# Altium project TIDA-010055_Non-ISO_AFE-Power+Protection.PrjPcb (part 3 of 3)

## Sheet TIDA-010055_Non-ISO_AFE-Power+Protection _Pg7.SchDoc: +24V INPUT SIMPLE SWITCHER + POWER MUX + MONITOR
size 431 x 279 mm; Date: Not shown in title block; ApprovedBy: Not shown in title block; CheckedBy: Not shown in title block; Author: Not shown in title block; CompanyName: Not shown in title block; DrawnBy: Sreenivasa; Engineer: Not shown in title block; Organization: Not shown in title block; Address1: Not shown in title block; Address2: Not shown in title block; Address3: Not shown in title block; Address4: Not shown in title block; DocumentNumber: 1; Revision: Use project parameter SCH_Rev; SheetNumber: 7; SheetTotal: 9; PageSetup: Record=PageOptions¦CenterHorizontal=True¦CenterVertical=True¦PrintScale=0.62¦XCorrection=1.00¦YCorrection=1.00¦PrintKind=0¦BorderSize=5000000¦LeftOffset=0¦BottomOffset=0¦Orientation=2¦PaperLength=1000¦PaperWidth=1000¦Scale=100¦PaperSource=15¦PrintQuality=600¦MediaType=1¦DitherType=10¦PrintScaleMode=1¦PaperKind=Letter
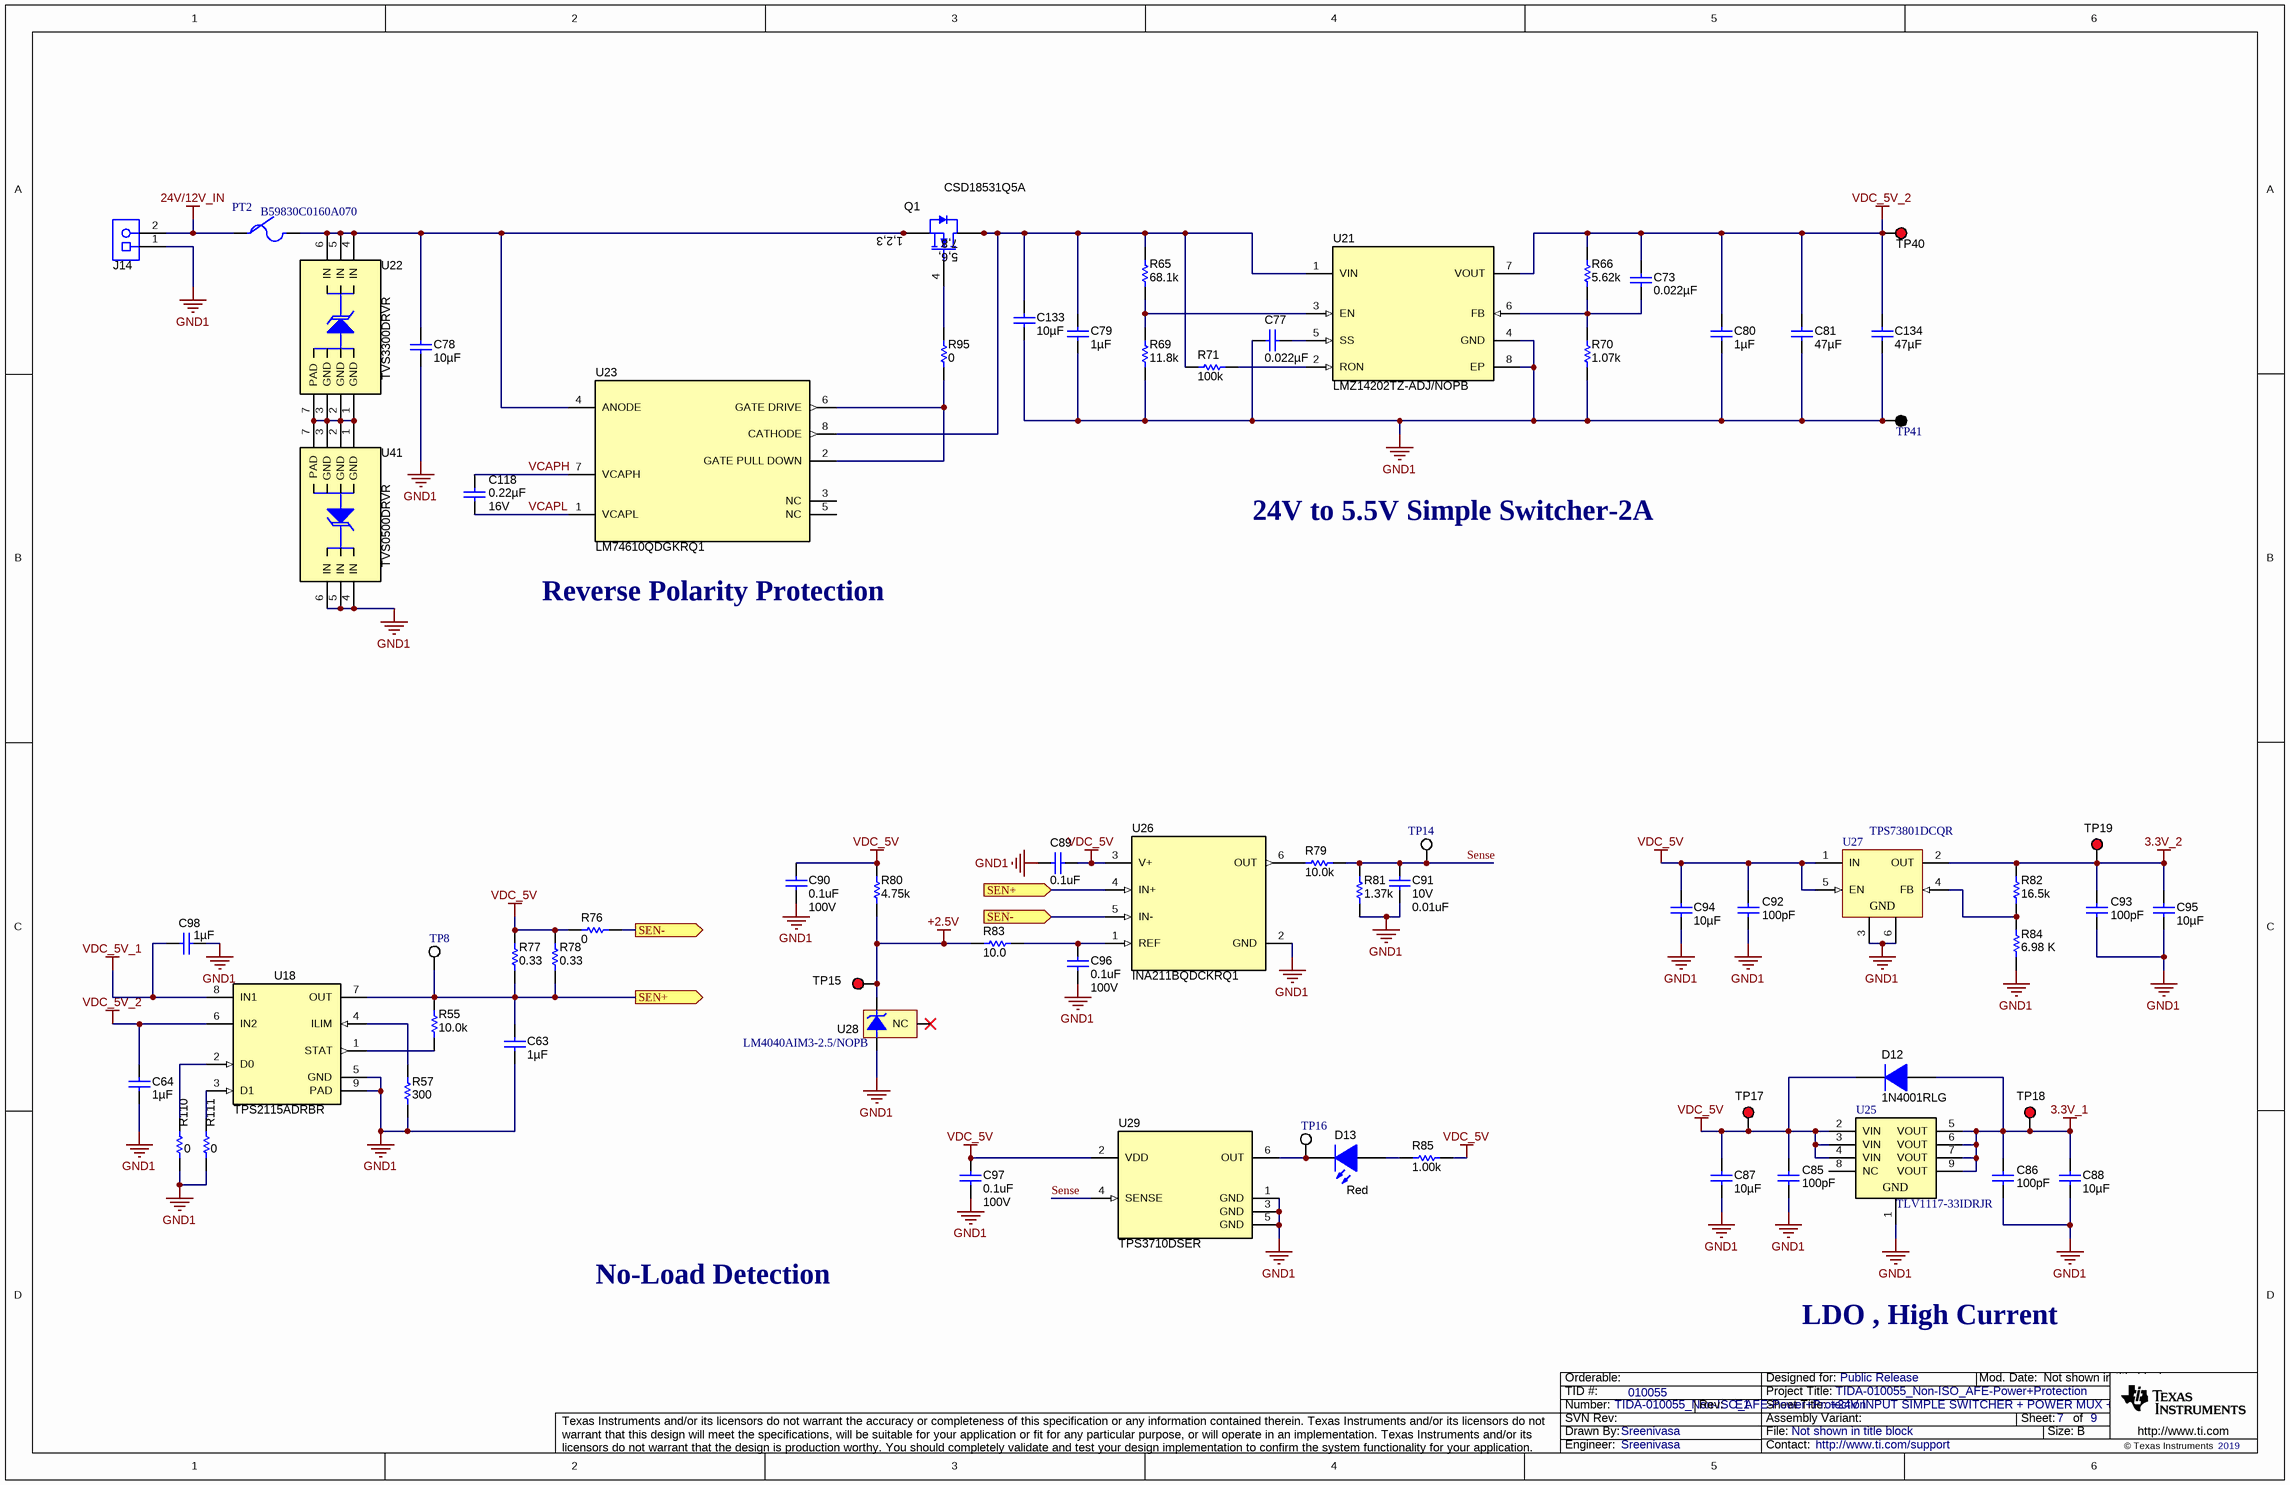
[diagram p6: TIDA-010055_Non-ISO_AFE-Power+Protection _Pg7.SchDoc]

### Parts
C63  ValueDisplayed: 1µF  [0603S]  (hidden comment: CGA3E1X7R1E105K080AC)
C64  ValueDisplayed: 1µF  [0603S]  (hidden comment: CGA3E1X7R1E105K080AC)
C73  ValueDisplayed: 0.022µF  [0805_HV]  (hidden comment: 08051C223JAT2A)
C77  ValueDisplayed: 0.022µF  [0805_HV]  (hidden comment: 08051C223JAT2A)
C78  ValueDisplayed: 10µF  [1210_270]  (hidden comment: C3225X7S1H106M250AB)
C79  ValueDisplayed: 1µF  [0603]  (hidden comment: UMK107BJ105KA-T)
C80  ValueDisplayed: 1µF  [0603]  (hidden comment: UMK107BJ105KA-T)
C81  ValueDisplayed: 47µF  [1206]  (hidden comment: EMK316BBJ476ML-T)
C85  ValueDisplayed: 100pF  [0603]  (hidden comment: 06031A101GAT2A)
C86  ValueDisplayed: 100pF  [0603]  (hidden comment: 06031A101GAT2A)
C87  ValueDisplayed: 10µF  [0805_HV]  (hidden comment: C2012X5R1E106K085AC)
C88  ValueDisplayed: 10µF  [0805_HV]  (hidden comment: C2012X5R1E106K085AC)
C89  ValueDisplayed: 0.1uF  [0805_HV]  (hidden comment: CMP-0007886-2)
C90  ValueDisplayed: 0.1uF  VDC_V: 100V  [0805_HV]  (hidden comment: CMP-0007886-2)
C91  VDC_V: 10V  ValueDisplayed: 0.01uF  [0603]  (hidden comment: 0603ZC103KAT2A)
C92  ValueDisplayed: 100pF  [0603]  (hidden comment: 06031A101GAT2A)
C93  ValueDisplayed: 100pF  [0603]  (hidden comment: 06031A101GAT2A)
C94  ValueDisplayed: 10µF  [0805_HV]  (hidden comment: C2012X5R1E106K085AC)
C95  ValueDisplayed: 10µF  [0805_HV]  (hidden comment: C2012X5R1E106K085AC)
C96  ValueDisplayed: 0.1uF  VDC_V: 100V  [0805_HV]  (hidden comment: CMP-0007886-2)
C97  ValueDisplayed: 0.1uF  VDC_V: 100V  [0805_HV]  (hidden comment: CMP-0007886-2)
C98  ValueDisplayed: 1µF  [0603S]  (hidden comment: CGA3E1X7R1E105K080AC)
C118  ValueDisplayed: 0.22µF  Value2: 16V  [0805_HV]  (hidden comment: 0805YC224KAT2A)
C133  ValueDisplayed: 10µF  [1210_270]  (hidden comment: C3225X7S1H106M250AB)
C134  ValueDisplayed: 47µF  [1206]  (hidden comment: EMK316BBJ476ML-T)
D12  1N4001RLG  [DO-41]
D13  value Red  [LED_LTST-C170_Red]  (hidden comment: CMP-0002829-2)
J14  1751248  [CONN_1751248]  (value not drawn)
PT2  B59830C0160A070  [POLYSWITCH_RXE135]
Q1  CSD18531Q5A  [DQJ0008A]
R55  ValueDisplayed: 10.0k  [0603]  (hidden comment: CRCW060310K0FKEA)
R57  ValueDisplayed: 300  [0603]  (hidden comment: RC0603FR-07300RL)
R65  ValueDisplayed: 68.1k  [0805_HV]  (hidden comment: ERJ-6ENF6812V)
R66  ValueDisplayed: 5.62k  [0805_HV]  (hidden comment: RT0805BRD075K62L)
R69  ValueDisplayed: 11.8k  [0805_HV]  (hidden comment: ERJ-6ENF1182V)
R70  ValueDisplayed: 1.07k  [0805_HV]  (hidden comment: ERJ-6ENF1071V)
R71  ValueDisplayed: 100k  [0805_HV]  (hidden comment: MCU08050C1003FP500)
R76  ValueDisplayed: 0  [0603]  (hidden comment: ERJ-3GEY0R00V)
R77  ValueDisplayed: 0.33  [1206]  (hidden comment: CSR1206FKR330)
R78  ValueDisplayed: 0.33  [1206]  (hidden comment: CSR1206FKR330)
R79  ValueDisplayed: 10.0k  [0603]  (hidden comment: CMP-0021998-2)
R80  ValueDisplayed: 4.75k  [0603]  (hidden comment: CMP-0022456-2)
R81  ValueDisplayed: 1.37k  [0603]  (hidden comment: RC0603FR-071K37L)
R82  ValueDisplayed: 16.5k  [0603]  (hidden comment: RC0603FR-0716K5L)
R83  ValueDisplayed: 10.0  [0603]  (hidden comment: CRCW060310R0FKEAHP)
R84  ValueDisplayed: 6.98 K  [0603]  (hidden comment: RT0603DRD076K98L)
R85  ValueDisplayed: 1.00k  [0603]  (hidden comment: ERJ-3EKF1001V)
R95  ValueDisplayed: 0  [0805_HV]  (hidden comment: CRCW08050000Z0EA)
R110  ValueDisplayed: 0  [0603]  (hidden comment: ERJ-3GEY0R00V)
R111  ValueDisplayed: 0  [0603]  (hidden comment: ERJ-3GEY0R00V)
TP8  5002  [Keystone5002]  (value not drawn)
TP14  5002  [Keystone5002]  (value not drawn)
TP15  5000  [Keystone5000]  (value not drawn)
TP16  5002  [Keystone5002]  (value not drawn)
TP17  5000  [Keystone5000]  (value not drawn)
TP18  5000  [Keystone5000]  (value not drawn)
TP19  5000  [Keystone5000]  (value not drawn)
TP40  5000  [Keystone5000]  (value not drawn)
TP41  5001  [Keystone5001]  (value not drawn)
U18  TPS2115ADRBR  [DRB0008B]
U21  LMZ14202TZ-ADJ/NOPB  [NDW0007A]
U22  TVS3300DRVR  [DRV0006A]
U23  LM74610QDGKRQ1  [DGK0008A_N]
U25  TLV1117-33IDRJR  [DRJ0008A]
U26  INA211BQDCKRQ1  [DCK0006A_L]
U27  TPS73801DCQR  [DCQ0006A_N]
U28  LM4040AIM3-2.5/NOPB  [MF03A_N]
U29  TPS3710DSER  [DSE0006A]
U41  TVS0500DRVR  [DRV0006A]

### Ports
SEN+ (in), SEN+ (out), SEN- (in), SEN- (out)

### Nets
3.3V_1: C86.2 C88.2 D12.2(A) TP18.1 U25.5(VOUT) U25.6(VOUT) U25.7(VOUT) U25.9(VOUT)
3.3V_2: C93.2 C95.2 R82.2 TP19.1 U27.2(OUT)
24V/12V_IN: J14.2 PT2.1
+2.5V: R80.1 R83.1 TP15.1 U28.1(+V)
GND1: C63.2 C64.2 C77.2 C78.2 C79.2 C80.2 C81.2 C85.1 C86.1 C87.1 C88.1 C89.1 C90.1 C91.2 C92.1 C93.1 C94.1 C95.1 C96.1 C97.1 C98.2 C133.2 C134.2 J14.1 R57.1 R69.1 R70.1 R81.1 R84.1 R110.1 R111.1 TP41.1 U18.5(GND) U18.9(PAD) U21.4(GND) U21.8(EP) U25.1(GND) U26.2(GND) U27.3(GND) U27.6(GND) U28.2(-V) U29.1(GND) U29.3(GND) U29.5(GND) U41.4(IN) U41.5(IN) U41.6(IN)
VDC_5V: C85.2 C87.2 C89.2 C90.2 C92.2 C94.2 C97.2 D12.1(K) R76.1 R77.2 R78.2 R80.2 R85.2 TP17.1 U25.2(VIN) U25.3(VIN) U25.4(VIN) U26.3(V+) U27.1(IN) U27.5(EN) U29.2(VDD)
VDC_5V_1: C98.1 U18.8(IN1)
VDC_5V_2: C64.1 C73.1 C80.1 C81.1 C134.1 R66.2 TP40.1 U18.6(IN2) U21.7(VOUT)
SEN+: C63.1 R55.2 R77.1 R78.1 TP8.1 U18.7(OUT) U26.4(IN+) ; port SEN+
SEN-: R76.2 U26.5(IN-) ; port SEN-
Sense: C91.1 R79.2 R81.2 TP14.1 U29.4(SENSE)
VCAPH: C118.1 U23.7(VCAPH)
VCAPL: C118.2 U23.1(VCAPL)
NetC73_2: C73.2 R66.1 R70.2 U21.6(FB)
NetC77_1: C77.1 U21.5(SS)
NetC78_1: C78.1 PT2.2 Q1.1(S) Q1.2(S) Q1.3(S) U22.4(IN) U22.5(IN) U22.6(IN) U23.4(ANODE)
NetC79_1: C79.1 C133.1 Q1.5(D) Q1.6(D) Q1.7(D) Q1.8(D) Q1.9(D) R65.2 R71.2 U21.1(VIN) U23.8(CATHODE)
NetC96_2: C96.2 R83.2 U26.1(REF)
NetD13_1: D13.1(A) R85.1
NetD13_2: D13.2(K) TP16.1 U29.6(OUT)
NetQ1_4: Q1.4(G) R95.2
NetR55_1: R55.1 U18.1(STAT)
NetR57_2: R57.2 U18.4(ILIM)
NetR65_1: R65.1 R69.2 U21.3(EN)
NetR71_1: R71.1 U21.2(RON)
NetR79_1: R79.1 U26.6(OUT)
NetR82_1: R82.1 R84.2 U27.4(FB)
NetR95_1: R95.1 U23.2(GATE_PULL_DOWN) U23.6(GATE_DRIVE)
NetR110_2: R110.2 U18.2(D0)
NetR111_2: R111.2 U18.3(D1)
NetU22_1: U22.1(GND) U22.2(GND) U22.3(GND) U22.7(PAD) U41.1(GND) U41.2(GND) U41.3(GND) U41.7(PAD)

Not connected (* = marked no-connect by the designer): U23 3(NC) 5(NC); U25 8(NC); U28 3(NC)*

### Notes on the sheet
- 24V to 5.5V Simple Switcher-2A
- Reverse Polarity Protection
- No-Load Detection
- LDO , High Current

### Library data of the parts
C63 C64 C98 = GRM188R71E105KA12D: CAP, CERM, 1 µF, 25 V, +/- 10%, X7R, 0603; Manufacturer: TDK Corporation; Polarized: N; CompType: Capacitor; Value: 1uF; U/M: EA; Cap_F: 0.000001; Tolerance_%: 10; Value1: Unknown; VDC_V: 25; Value2: 25V; TaMin_C: -55; TaMax_C: 125; Cap_Case: 0603; AEC Category: Q200
C73 C77 = 08051C223JAT2A: CAP, CERM, 0.022 µF, 100 V,+/- 5%, X7R, 0805; Manufacturer: AVX; Polarized: N; CompType: Capacitor; Value: 0.022uF; U/M: EA; Cap_F: 0.000000022; Tolerance_%: 5; ESR_ohm: 0.052; Value1: 0.052 ohm; VDC_V: 100; Value2: 100V; TaMin_C: -55; TaMax_C: 125; Cap_Case: 0805; SizeArea_mm2: 2.5; SizeAreaWB_mm2: 6.75; SizeX_mm: 2; SizeY_mm: 1.25; SizeZ_mm: 1.45; AEC Category: Q200; Green_Lifecycle: Active; Green_REACh: Passed
C78 C133 = GRM32ER71J106KA12L: CAP, CERM, 10µF ±20% 50V Ceramic Capacitor X7R 1210; Manufacturer: Taiyo Yuden; Polarized: N; Value: 10uF; U/M: EA; Cap_F: 0.00001; Tolerance_%: 10; Value1: Unknown; VDC_V: 63; Value2: 63V; TaMin_C: -55; TaMax_C: 125; Cap_Case: 1210; SizeArea_mm2: 8; SizeAreaWB_mm2: 14.7; SizeX_mm: 3.2; SizeY_mm: 2.5; SizeZ_mm: 2.7; AEC Category: Q200
C79 C80 = UMK107AB7105KA-T: CAP, CERM,  1UF 50V X5R 0603; Manufacturer: Taiyo Yuden; Polarized: N; CompType: Capacitor; U/M: EA; Cap_F: 0.000001; Tolerance_%: 10; VDC_V: 50; TempCo: X7R; TaMin_C: -55; TaMax_C: 125; SizeArea_mm2: 1.28; SizeAreaWB_mm2: 4.68; SizeX_mm: 1.6; SizeY_mm: 0.8; SizeZ_mm: 1; AEC Category: Q200; Green_Lifecycle: Active; Green_REACh: Passed
C81 = C3216X5R1C476M160AB: CAP, CERM,47µF ±20% 16V Ceramic Capacitor JB 1206; Manufacturer: Taiyo Yuden; Polarized: N; Value: 47uF; U/M: EA; Cap_F: 0.000047; Tolerance_%: 15; VDC_V: 16; TempCo: X5R; TaMin_C: -55; TaMax_C: 85; SizeArea_mm2: 5.12; SizeAreaWB_mm2: 10.92; SizeX_mm: 3.2; SizeY_mm: 1.6; SizeZ_mm: 1.35; AEC Category: Q200; Green_Lifecycle: Active; Green_REACh: Passed
C85 C86 C92 C93 = 06035A101JAT2A: CAP, CERM, 100 pF, 50 V, +/- 5%, C0G/NP0, 0603; Manufacturer: AVX; Polarized: N; CompType: Capacitor; Value: 100pF; U/M: EA; Cap_F: 0.0000000001; Tolerance_%: 5; ESR_ohm: 0.119; Value1: 0.119 ohm; VDC_V: 50; Value2: 50V; TaMin_C: -55; TaMax_C: 125; SizeArea_mm2: 1.28; SizeAreaWB_mm2: 4.68; SizeX_mm: 1.6; SizeY_mm: 0.8; SizeZ_mm: 1; AEC Category: Q200
C87 C88 C94 C95 = GRM21BR61E106KA73L: CAP, CERM, 10 µF, 25 V, +/- 10%, X5R, 0805; Manufacturer: TDK Corporation; Polarized: N; CompType: Capacitor; Value: 10uF; U/M: EA; Cap_F: 0.00001; Tolerance_%: 10; Value1: Unknown; VDC_V: 25; Value2: 25V; TaMin_C: -55; TaMax_C: 85; Cap_Case: 0805; AEC Category: Q200
C89 = CMP-0007886-2: CAP, CERM, 0.1 uF, 100 V, +/- 10%, X7R, 0805; PartNumber: C2012X7R2A104K125AA; Manufacturer: TDK; Polarized: N; Value: 0.1uF; U/M: EA; Cap_F: 100nF; ESR_ohm: 0.020726; Value1: 0.020726 ohm; VDC_V: 100V; IRMS_A: 1.456A; TaMin_C: -55°C; TaMax_C: 125°C; Cap_Case: 0805; SizeArea_mm2: 2.5; SizeAreaWB_mm2: 6.75; SizeX_mm: 2; SizeY_mm: 1.25; SizeZ_mm: 1.45; AEC Category: Q200
C90 C96 C97 = CMP-0007886-2: CAP, CERM, 0.1 uF, 100 V, +/- 10%, X7R, 0805; PartNumber: C2012X7R2A104K125AA; Manufacturer: TDK; Polarized: N; CompType: Capacitor; Value: 0.1uF; U/M: EA; Cap_F: 100nF; ESR_ohm: 0.020726; Value1: 0.020726 ohm; IRMS_A: 1.456A; TaMin_C: -55°C; TaMax_C: 125°C; Cap_Case: 0805; SizeArea_mm2: 2.5; SizeAreaWB_mm2: 6.75; SizeX_mm: 2; SizeY_mm: 1.25; SizeZ_mm: 1.45; AEC Category: Q200
C91 = CMP-0006814-2: CAP, CERM, 0.01 uF, 10 V, +/- 10%, X7R, 0603; Manufacturer: AVX; TaMin_C: -55°C; Polarized: N; SizeAreaWB_mm2: 4.68; Value1: Unknown; U/M: EA; Value: 0.01uF; TaMax_C: 125°C; SizeZ_mm: 1; SizeX_mm: 1.6; SizeY_mm: 0.8; SizeArea_mm2: 1.28; Cap_F: 10nF; AEC Category: Q200
C118 = 0805YC224KAT2A: CAP, CERM, 0.22 µF, 16 V, +/- 10%, X7R, 0805; Manufacturer: AVX; Polarized: N; CompType: Capacitor; Value: 0.22uF; U/M: EA; Cap_F: 0.00000022; Tolerance_%: 10; ESR_ohm: 0.016; Value1: 0.016 ohm; VDC_V: 16; TaMin_C: -55; TaMax_C: 125; Cap_Case: 0805
C134 = C3216X5R1C476M160AB: CAP, CERM, 47 µF, 16 V,+/- 15%, X5R, 1206; Manufacturer: Taiyo Yuden; Polarized: N; CompType: Capacitor; Value: 47uF; U/M: EA; Cap_F: 0.000047; Tolerance_%: 15; VDC_V: 16; Value2: 16V; TaMin_C: -55; TaMax_C: 85; SizeArea_mm2: 5.12; SizeAreaWB_mm2: 10.92; SizeX_mm: 3.2; SizeY_mm: 1.6; SizeZ_mm: 1.35; AEC Category: Q200; Green_Lifecycle: Active; Green_REACh: Passed
D12 = 1N4002-T: Diode Standard 50V 1A Through Hole DO-41; Manufacturer: ON Semiconductor; U/M: EA; Vf_V: 1; Value: 100V; Value2: 1V; Vr_V: 100; TJmax_C: 150; Type: P-N; SizeAreaWB_mm2: 43.424; SizeArea_mm2: 19.584; SizeX_mm: 7.2; SizeY_mm: 2.72; SizeZ_mm: 23.4; AEC Category: Q101; Green_Lifecycle: NRND; Green_REACh: Passed
D13 = CMP-0002829-2: LED, Red, SMD; PartNumber: LTST-C170KRKT; Manufacturer: Lite-On; Type: AlInGaP; Vf_V: 2V; Io_A: 20mA; Value1: W; SizeAreaWB_mm2: 6.75; SizeArea_mm2: 2.5; SizeX_mm: 2; SizeY_mm: 1.25; SizeZ_mm: 1.2; U/M: EA
J14 = 1751248: Conn Term Block, 2POS, 3.5mm, TH; Manufacturer: Phoenix Contact; CompType: Terminal Block; SymbolCreator: a0412235
PT2 = POLYSWITCH_RXE135: PTC THERMISTOR C 830-A 160-A 70; Manufacturer: Raychem; Manufacturer: EPCOS (TDK); Area: 93750
Q1 = CMP-0000810-1: MOSFET, N-CH, 60 V, 100 A, DQJ0008A (VSONP-8); Alternate Manufacturer: None; Manufacturer: Texas Instruments; SizeZ_mm: 1.1; ChType: N; Value2: 36 nC; Value1: 0.005; VdsMax_V: 60V; SizeX_mm: 6; SizeY_mm: 4.9; Vgs_V: 20V; Value: 60V; Rdson45_ohm: 5.8m; SizeArea_mm2: 29.4; AEC Category: Q101; IdsMax_A: 100A; SizeAreaWB_mm2: 55.2; U/M: EA; QgTyp_nC: 36
R55 = CRCW060310K0FKEA: RES, 10.0 k, 1%, 0.1 W, 0603; Manufacturer: Vishay-Dale; CompType: Resistor; Value: 10.0k; Res_ohm: 10000; Value_Code: 10k0; Tolerance_%: 1; Power_W: 0.1; Value2: 0.1W; VDC_V: 75; TempCo: 100 ppm/C; SizeArea_mm2: 1.28; SizeX_mm: 1.6; SizeY_mm: 0.8; EIA_Code: E96; U/M: EA; AEC Category: Q200; Green_Lifecycle: Active; Green_REACh: Passed
R57 = RC0603FR-07300RL: RES, 300, 1%, 0.1 W, 0603; Manufacturer: Yageo America; CompType: Resistor; Value: 300; Value_Code: 300R; Tolerance_%: 1; Power_W: 0.1; Value2: 0.1W; VDC_V: 150; TempCo: 200 ppm/C; SizeArea_mm2: 1.28; SizeX_mm: 1.6; SizeY_mm: 0.8; U/M: EA; AEC Category: Q200; Green_Lifecycle: Active; Green_REACh: Passed
R65 = ERJ-6ENF6812V: RES, 68.1 k, 1%, 0.125 W, 0805; Manufacturer: Panasonic; CompType: Resistor; Value: 68.1k; Res_ohm: 68100; Value_Code: 68k1; Tolerance_%: 1; Power_W: 0.125; Value2: 0.125W; TempCo: 100 ppm/C; SizeArea_mm2: 2.5; SizeX_mm: 2; SizeY_mm: 1.25; SizeZ_mm: 1.45; EIA_Code: E96; U/M: EA; AEC Category: Q200
R66 = RT0805BRD075K62L: RES, 5.62 k, 0.1%, 0.125 W, 0805; Manufacturer: Yageo America; CompType: Resistor; Value: 5.62k; Res_ohm: 5620; Value_Code: 5k62; Tolerance_%: 0.1; Power_W: 0.125; Value2: 0.125W; VDC_V: 150; TempCo: 25 ppm/C; SizeArea_mm2: 2.5; SizeX_mm: 2; SizeY_mm: 1.25; SizeZ_mm: 1.45; EIA_Code: E192; U/M: EA; AEC Category: Q200
R69 = ERJ-6ENF1182V: RES, 11.8 k, 1%, 0.125 W, 0805; Manufacturer: Panasonic; CompType: Resistor; Value: 11.8k; Res_ohm: 11800; Value_Code: 11k8; Tolerance_%: 1; Power_W: 0.125; Value2: 0.125W; TempCo: 100 ppm/C; SizeArea_mm2: 2.5; SizeX_mm: 2; SizeY_mm: 1.25; SizeZ_mm: 1.45; EIA_Code: E96; U/M: EA; AEC Category: Q200; Green_Lifecycle: Active; Green_REACh: Passed
R70 = ERJ-6ENF1071V: RES, 1.07 k, 1%, 0.125 W, 0805; Manufacturer: Panasonic; CompType: Resistor; Value: 1.07k; Res_ohm: 1070; Value_Code: 1k07; Tolerance_%: 1; Power_W: 0.125; Value2: 0.125W; TempCo: 100 ppm/C; SizeArea_mm2: 2.5; SizeX_mm: 2; SizeY_mm: 1.25; SizeZ_mm: 1.45; EIA_Code: E96; U/M: EA; AEC Category: Q200
R71 = MCU08050C1003FP500: RES, 100 k, 1%, 0.2 W, 0805; Manufacturer: Vishay/Beyschlag; CompType: Resistor; Value: 100k; Res_ohm: 100000; Tolerance_%: 1; Power_W: 0.2; Value2: 0.2W; VDC_V: 150; TempCo: 50 ppm/C; SizeArea_mm2: 2.5; SizeX_mm: 2; SizeY_mm: 1.25; SizeZ_mm: 1.45; EIA_Code: E96; U/M: EA; AEC Category: Q200; AEC Qualified: N
R76 R110 R111 = ERJ-3GEY0R00V: RES, 0, 5%, 0.1 W, 0603; Manufacturer: Panasonic; CompType: Resistor; Value: 0; Value_Code: 0000; Tolerance_%: 5; Power_W: 0.1; Value2: 0.1W; VDC_V: 50; TempCo: 600 ppm/C; SizeArea_mm2: 1.28; SizeX_mm: 1.6; SizeY_mm: 0.8; SizeZ_mm: 1; EIA_Code: E24; U/M: EA; AEC Category: Q200; Green_Lifecycle: Active; Green_REACh: Passed
R77 R78 = CSR1206FKR330: RES, 0.33, 1%, 0.5 W, 1206; Manufacturer: Stackpole Electronics Inc; CompType: Resistor; Value: 0.33; Value_Code: R330; Tolerance_%: 1; Power_W: 0.5; Value2: 0.5W; TempCo: 100 ppm/C; SizeArea_mm2: 5.12; SizeX_mm: 3.2; SizeY_mm: 1.6; SizeZ_mm: 1.35; EIA_Code: E96; U/M: EA; AEC Category: Q200
R79 = CMP-0021998-2: RES, 10.0 k, 1%, 0.1 W, 0603; PartNumber: CRCW060310K0FKEA; Manufacturer: Vishay-Dale; Value: 10.0k; Res_ohm: 10k; Value_Code: 10k0; Power_W: 100mW; Value2: 0.1W; VDC_V: 75V; TempCo: 100 ppm/C; SizeArea_mm2: 1.28; SizeX_mm: 1.6; SizeY_mm: 0.8; SizeZ_mm: 1; EIA_Code: E96; U/M: EA; AEC Category: Q200
R80 = CMP-0022456-2: RES, 4.75 k, 1%, 0.1 W, 0603; PartNumber: CRCW06034K75FKEA; Manufacturer: Vishay-Dale; Value: 4.75k; Value_Code: 4k75; Power_W: 100mW; Value2: 0.1W; VDC_V: 75V; TempCo: 100 ppm/C; SizeArea_mm2: 1.28; SizeX_mm: 1.6; SizeY_mm: 0.8; SizeZ_mm: 1; EIA_Code: E96; U/M: EA; AEC Category: Q200
R81 = RC0603FR-071K37L: RES, 1.37 k, 1%, 0.1 W, 0603; Manufacturer: Yageo America; CompType: Resistor; Value: 1.37k; Res_ohm: 1370; Value_Code: 1k37; Tolerance_%: 1; Power_W: 0.1; Value2: 0.1W; VDC_V: 150; TempCo: 200 ppm/C; SizeArea_mm2: 1.28; SizeX_mm: 1.6; SizeY_mm: 0.8; EIA_Code: E96; U/M: EA; AEC Category: Q200
R82 = RC0603FR-0716K5L: RES, 16.5 k, 1%, 0.1 W, 0603; Manufacturer: Yageo America; CompType: Resistor; Value: 16.5k; Res_ohm: 16500; Value_Code: 16k5; Tolerance_%: 1; Power_W: 0.1; Value2: 0.1W; VDC_V: 150; TempCo: 200 ppm/C; SizeArea_mm2: 1.28; SizeX_mm: 1.6; SizeY_mm: 0.8; EIA_Code: E96; U/M: EA; AEC Category: Q200; Green_Lifecycle: Active; Green_REACh: Passed
R83 = CMP-0022004-2: RES, 10.0, 1%, 0.25 W, 0603; Manufacturer: Vishay-Dale; Value: 10.0; Res_ohm: 10; Value_Code: 10R0; Power_W: 250mW; Value2: 0.25W; VDC_V: 75V; TempCo: 100 ppm/C; SizeArea_mm2: 1.28; SizeX_mm: 1.6; SizeY_mm: 0.8; SizeZ_mm: 1; EIA_Code: E96; U/M: EA; AEC Category: Q200
R84 = RT0603DRE076R9L: 6.98 kOhms ±0.5% 0.1W, 1/10W Chip Resistor 0603 (1608 Metric) Thin Film; Manufacturer: Yageo America; Value: 6.98 K; Res_ohm: 6.9; Tolerance_%: 0.5; Power_W: 0.1; VDC_V: 75; TempCo: 50 ppm/C; SizeArea_mm2: 1.28; SizeX_mm: 1.6; SizeY_mm: 0.8; SizeZ_mm: 1; EIA_Code: E192; U/M: EA; AEC Category: Q200
R85 = ERJ-3EKF1001V: RES, 1.00 k, 1%, 0.1 W, AEC-Q200 Grade 0, 0603; Manufacturer: Panasonic; CompType: Resistor; Value: 1.00k; Res_ohm: 1000; Value_Code: 1k00; Tolerance_%: 1; Power_W: 0.1; Value2: 0.1W; VDC_V: 75; TempCo: 100 ppm/C; SizeArea_mm2: 1.28; SizeX_mm: 1.6; SizeY_mm: 0.8; EIA_Code: E96; U/M: EA; AEC Category: Q200; AEC Qualified: Y; AEC Grade: 0; Green_Lifecycle: Active; Green_REACh: Passed
R95 = CRCW08050000Z0EA: RES, 0, 5%, 0.125 W, 0805; Manufacturer: Vishay-Dale; CompType: Resistor; Value: 0; Value_Code: 0000; Tolerance_%: 5; Power_W: 0.125; Value2: 0.125W; VDC_V: 150; TempCo: 200 ppm/C; EIA_Code: E24; U/M: EA
TP8 TP14 TP16 = 5002: Test Point, Miniature, White, TH; Manufacturer: Keystone; CompType: Test Point Loop; ContactFinish: Silver; Green_Lifecycle: Active; Green_REACh: Passed
TP15 TP17-TP19 TP40 = 5000: Test Point, Miniature, Red, TH; Manufacturer: Keystone; CompType: Test Point Loop; ContactFinish: Silver
TP41 = 5001: Test Point, Miniature, Black, TH; Manufacturer: Keystone; CompType: Test Point Loop; ContactFinish: Silver; Green_Lifecycle: Active; Green_REACh: Passed
U18 = TPS2115ADRBR: AUTOSWITCHING POWER MUX, DRB0008B (VSON-8); Alternate PartNumber: TPS2115ADRBT; Manufacturer: Texas Instruments; SymbolCreator: a0411947; SizeArea_mm2: 9; SizeAreaWB_mm2: 16; SizeX_mm: 3; SizeZ_mm: 1; CompType: IC; U/M: EA; Green_Lifecycle: Active; Green_REACh: Passed
U21 = CMP-0080899-1: SIMPLE SWITCHER (R) 6V to 42V, 2A Power Module in Leaded SMT-TO Package, NDW0007A (TO-PMOD-7); Alternate PartNumber: LMZ14202TZX-ADJ/NOPB; Alternate Manufacturer: Texas Instruments; SizeAreaWB_mm2: 191.7632; SizeZ_mm: 4.7; SizeX_mm: 13.77; SizeY_mm: 10.16; SizeArea_mm2: 139.9032; CompType: IC; AEC Qualified: N; AEC Category: Q200
U22 = CMP-0013424-7: 33-V Precision Surge Protection Clamp, DRV0006A (WSON-6); Manufacturer: Texas Instruments; Alternate PartNumber: TVS3300DRVT; SizeX_mm: 2; CompType: IC; SizeZ_mm: 0.8; SizeArea_mm2: 4; SizeAreaWB_mm2: 9; U/M: EA
U23 = CMP-0076397-2: Zero Iq Reverse Polarity Protection Smart Diode Controller, DGK0008A (VSSOP-8); Manufacturer: Texas Instruments; SizeAreaWB_mm2: 23.6; SizeArea_mm2: 14.7; SizeZ_mm: 1.1; Green_REACh: Passed; SizeY_mm: 3; Green_Lifecycle: Active; CompType: IC; SizeX_mm: 4.9; AEC Category: Q200; AEC Qualified: Y
U25 = TLV1117-33IDRJR: LDO with 4.7 to 15 V Input and 3.3 V Output, -40 to 125 degC, 8-Pin SON (DRJ), Green (RoHS & no Sb/Br); Manufacturer: Texas Instruments; Alternate PartNumber: Equivalent; Iout(Max)(A): 0.8; Iq(Typ)(mA): 5; Vin(Max)(V): 15; Vin(Min)(V): 4.7; Vout(Max)(V): 3.3
U26 = CMP-0076880-1: Automotive-Grade, Voltage Output, Low- or High-Side Measurement, Bidirectional, Zero-Drift Series, Current-Shunt Monitor, DCK0006A (SOT-SC70-6); Manufacturer: Texas Instruments; SizeAreaWB_mm2: 9.3; SizeArea_mm2: 4.2; SizeZ_mm: 1.1; SizeY_mm: 2.0; U/M: EA; CompType: IC; SizeX_mm: 2.1
U27 = CMP-0036669-1: Single Output Fast Transient Response LDO, 1 A, Adjustable 1.2 to 20 V Output, 2.2 to 20 V Input, 6-pin SOT-223 (DCQ), -40 to 125 degC, Green (RoHS & no Sb/Br); Manufacturer: Texas Instruments; Vout Adj(Max)(V): 20; Iout(Max)(A): 1; Vdo(Typ)(mV): 300; SubFamily: Single Channel LDO; Vin(Min)(V): 2.2; Vout Adj(Min)(V): 1.2
U28 = LM4040AIM3-2.5/NOPB: Precision Micropower Shunt Voltage Reference, 3-pin SOT-23, Pb-Free; Manufacturer: Texas Instruments; PackageTopMarking: R2A*XTT; PowerWise: N; CompType: Voltage Reference IC
U29 = CMP-0074247-1: Wide VIN Voltage Detector, DSE0006A (WSON-6); Alternate PartNumber: TPS3710DSET; Alternate Manufacturer: Texas Instruments; SizeAreaWB_mm2: 6.25; U/M: EA; SizeZ_mm: 0.8; SizeX_mm: 1.5; SizeArea_mm2: 2.25; CompType: IC
U41 = CMP-0077837-1: 5-V Precision Surge Protection Clamp, DRV0006A (WSON-6); Alternate Manufacturer: Texas Instruments; SizeAreaWB_mm2: 9.0; SizeZ_mm: 0.8; SizeX_mm: 2.0; SizeArea_mm2: 4.0; CompType: IC; AEC Qualified: N; AEC Category: Q200

## Sheet TIDA-010055_Non-ISO_AFE-Power+Protection _Pg8.SchDoc: +24V SIMPLE SWITCHER
size 431 x 279 mm; Date: Not shown in title block; ApprovedBy: Not shown in title block; CheckedBy: Not shown in title block; Author: Not shown in title block; CompanyName: Not shown in title block; DrawnBy: Sreenivasa; Engineer: Not shown in title block; Organization: Not shown in title block; Address1: Not shown in title block; Address2: Not shown in title block; Address3: Not shown in title block; Address4: Not shown in title block; DocumentNumber: 1; Revision: Use project parameter SCH_Rev; SheetNumber: 8; SheetTotal: 9; PageSetup: Record=PageOptions¦CenterHorizontal=True¦CenterVertical=True¦PrintScale=0.62¦XCorrection=1.00¦YCorrection=1.00¦PrintKind=0¦BorderSize=5000000¦LeftOffset=0¦BottomOffset=0¦Orientation=2¦PaperLength=1000¦PaperWidth=1000¦Scale=100¦PaperSource=15¦PrintQuality=600¦MediaType=1¦DitherType=10¦PrintScaleMode=1¦PaperKind=Letter
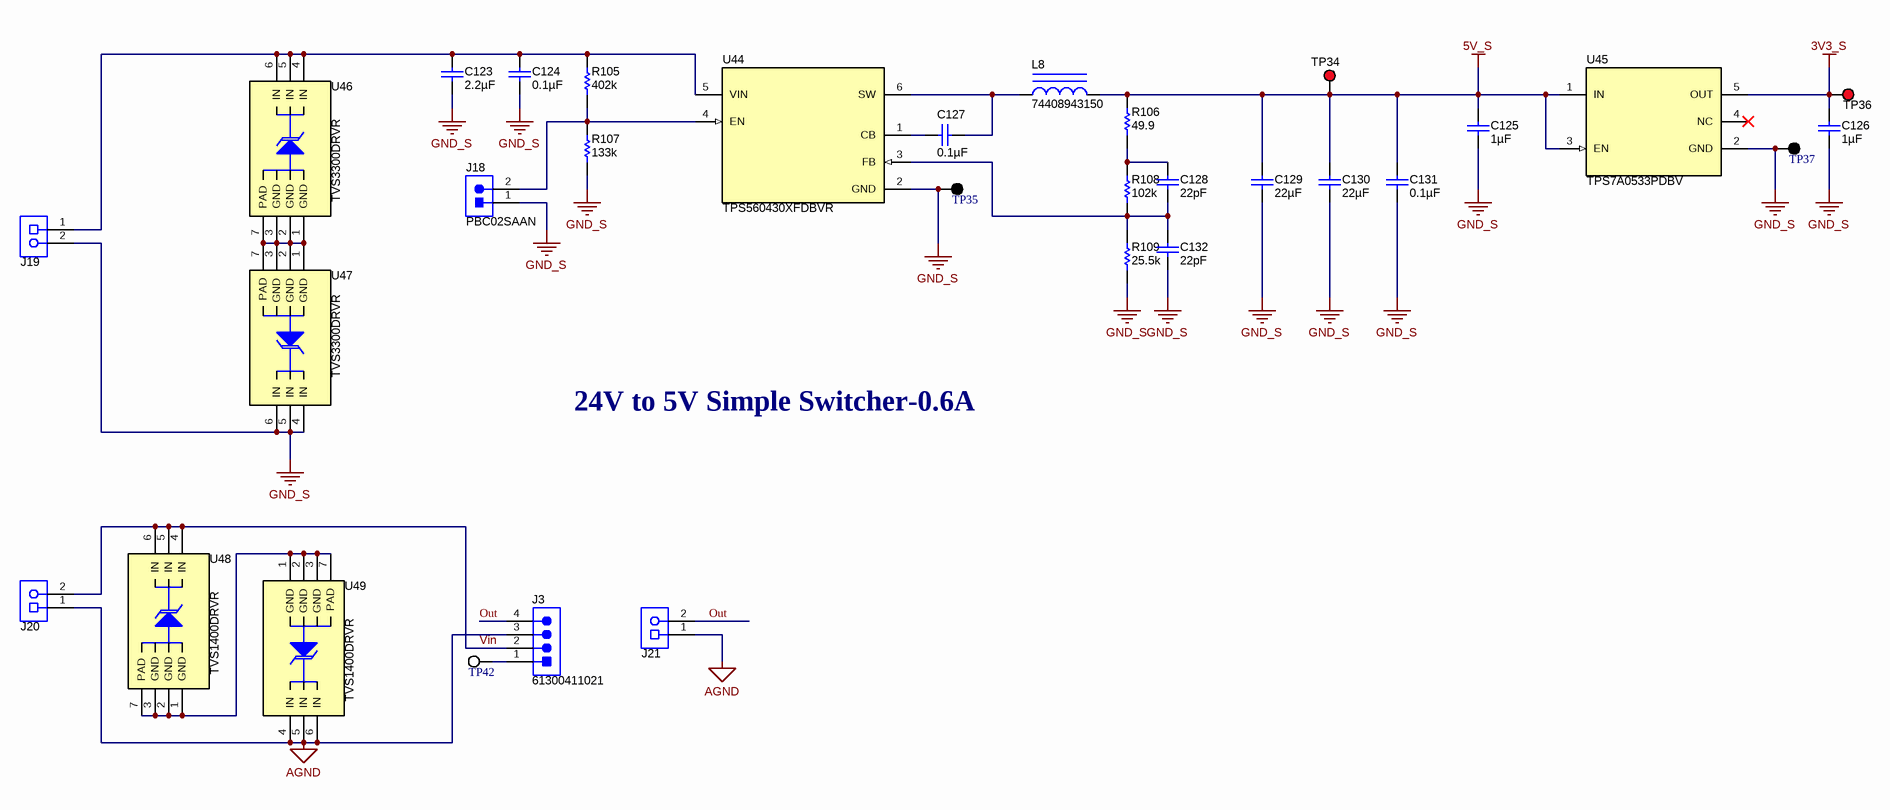
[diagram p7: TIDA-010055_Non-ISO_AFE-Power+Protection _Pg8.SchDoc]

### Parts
C123  ValueDisplayed: 2.2µF  [1206]  (hidden comment: UMK316B7225KL-T)
C124  ValueDisplayed: 0.1µF  [0603]  (hidden comment: C0603X124K5RAC7867)
C125  ValueDisplayed: 1µF  [0603]  (hidden comment: UMK107BJ105KA-T)
C126  ValueDisplayed: 1µF  [0603]  (hidden comment: UMK107BJ105KA-T)
C127  ValueDisplayed: 0.1µF  [0603]  (hidden comment: C0603X124K5RAC7867)
C128  ValueDisplayed: 22pF  [0603]  (hidden comment: 06035A220JAT2A)
C129  ValueDisplayed: 22µF  [1206_180]  (hidden comment: CL31B226MPHNNNE)
C130  ValueDisplayed: 22µF  [1206_180]  (hidden comment: CL31B226MPHNNNE)
C131  ValueDisplayed: 0.1µF  [0603]  (hidden comment: C0603X124K5RAC7867)
C132  ValueDisplayed: 22pF  [0603]  (hidden comment: 06035A220JAT2A)
J3  61300411021  [Wurth_61300411021]
J18  PBC02SAAN  [Sullins_PBC02SAAN]
J19  1751248  [CONN_1751248]  (value not drawn)
J20  1751248  [CONN_1751248]  (value not drawn)
J21  1751248  [CONN_1751248]  (value not drawn)
L8  74408943150  [WE-SPC_4838]
R105  ValueDisplayed: 402k  [0603]  (hidden comment: CRCW0603402KFKEA)
R106  ValueDisplayed: 49.9  [0603]  (hidden comment: CRCW060349R9FKEA)
R107  ValueDisplayed: 133k  [0603]  (hidden comment: CRCW0603133KFKEA)
R108  ValueDisplayed: 102k  [0603]  (hidden comment: CRCW0603102KFKEA)
R109  ValueDisplayed: 25.5k  [0603]  (hidden comment: CRCW060325K5FKEA)
TP34  5000  [Keystone5000]  (value not drawn)
TP35  5001  [Keystone5001]  (value not drawn)
TP36  5000  [Keystone5000]  (value not drawn)
TP37  5001  [Keystone5001]  (value not drawn)
TP42  5002  [Keystone5002]  (value not drawn)
U44  TPS560430XFDBVR  [DBV0006A_N]
U45  TPS7A0533PDBV  [DBV0005A_N]
U46  TVS3300DRVR  [DRV0006A]
U47  TVS3300DRVR  [DRV0006A]
U48  TVS1400DRVR  [DRV0006A]
U49  TVS1400DRVR  [DRV0006A]

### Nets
3V3_S: C126.1 TP36.1 U45.5(OUT)
5V_S: C125.1 C129.1 C130.1 C131.2 L8.2 R106.2 TP34.1 U45.1(IN) U45.3(EN)
AGND: J3.3 J20.1 J21.1 U49.4(IN) U49.5(IN) U49.6(IN)
GND_S: C123.2 C124.2 C125.2 C126.2 C129.2 C130.2 C131.1 C132.2 J18.1 J19.2 R107.1 R109.1 TP35.1 TP37.1 U44.2(GND) U45.2(GND) U47.4(IN) U47.5(IN) U47.6(IN)
Out: J3.4 J21.2
Vin: J3.2 J20.2 U48.4(IN) U48.5(IN) U48.6(IN)
NetC123_1: C123.1 C124.1 J19.1 R105.2 U44.5(VIN) U46.4(IN) U46.5(IN) U46.6(IN)
NetC127_1: C127.1 U44.1(CB)
NetC127_2: C127.2 L8.1 U44.6(SW)
NetC128_1: C128.1 R106.1 R108.2
NetC128_2: C128.2 C132.1 R108.1 R109.2 U44.3(FB)
NetJ3_1: J3.1 TP42.1
NetJ18_2: J18.2 R105.1 R107.2 U44.4(EN)
NetU46_1: U46.1(GND) U46.2(GND) U46.3(GND) U46.7(PAD) U47.1(GND) U47.2(GND) U47.3(GND) U47.7(PAD)
NetU48_1: U48.1(GND) U48.2(GND) U48.3(GND) U48.7(PAD) U49.1(GND) U49.2(GND) U49.3(GND) U49.7(PAD)

Not connected (* = marked no-connect by the designer): U45 4(NC)*

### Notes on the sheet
- 24V to 5V Simple Switcher-0.6A

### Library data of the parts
C123 = UMK316B7225KL-T: CAP, CERM, 2.2 µF, 50 V,+/- 10%, X7R, 1206; Manufacturer: Taiyo Yuden; Polarized: N; CompType: Capacitor; Value: 2.2uF; U/M: EA; Cap_F: 0.0000022; Tolerance_%: 10; VDC_V: 50; Value2: 50V; TaMin_C: -55; TaMax_C: 125; SizeArea_mm2: 5.12; SizeAreaWB_mm2: 10.92; SizeX_mm: 3.2; SizeY_mm: 1.6; SizeZ_mm: 1.35; AEC Category: Q200
C124 C127 C131 = GRM188R71H104KA93D: CAP, CERM, 0.12µF ±10% 50V Ceramic Capacitor X7R 0603; Manufacturer: KEMET; Polarized: N; Value: 0.1uF; U/M: EA; Cap_F: 0.0000001; Tolerance_%: 10; VDC_V: 50; TaMin_C: -55; TaMax_C: 125; SizeArea_mm2: 1.28; SizeAreaWB_mm2: 4.68; SizeX_mm: 1.6; SizeY_mm: 0.8; SizeZ_mm: 1; AEC Category: Q200; Green_Lifecycle: Active; Green_REACh: Passed
C125 C126 = UMK107AB7105KA-T: as C79 on sheet TIDA-010055_Non-ISO_AFE-Power+Protection _Pg7
C128 C132 = 06035A220JAT2A: CAP, CERM, 22 pF, 50 V,+/- 5%, C0G/NP0, 0603; Manufacturer: AVX; Polarized: N; CompType: Capacitor; Value: 22pF; U/M: EA; Cap_F: 0.000000000022; Tolerance_%: 5; ESR_ohm: 0.259; Value1: 0.259 ohm; VDC_V: 50; Value2: 50V; TaMin_C: -55; TaMax_C: 125; SizeArea_mm2: 1.28; SizeAreaWB_mm2: 4.68; SizeX_mm: 1.6; SizeY_mm: 0.8; SizeZ_mm: 1; AEC Category: Q200; Green_Lifecycle: Active; Green_REACh: Passed
C129 C130 = GRM31CR71A226KE15L: CAP, CERM, 22 µF, 10 V,+/- 10%, X7R, 1206; Manufacturer: Samsung Electro-Mechanics; Polarized: N; CompType: Capacitor; Value: 22uF; U/M: EA; Cap_F: 0.000022; Tolerance_%: 10; Value2: 10V; TaMin_C: -55; TaMax_C: 125; Cap_Case: 1206; SizeArea_mm2: 5.12; SizeAreaWB_mm2: 10.92; SizeX_mm: 3.2; SizeY_mm: 1.6; SizeZ_mm: 1.8; AEC Category: Q200; Green_Lifecycle: Active; Green_REACh: Passed
J3 = 61300411021: Header, 2.54 mm, 4x1, Gold, R/A, TH; Manufacturer: Wurth Elektronik; SymbolCreator: a0412235; Pitch_mm: 2.54; Gender: Male; Shrouded: N; Row_Count: 1
J18 = PBC02SAAN: Header, 100mil, 2x1, Gold, TH; Manufacturer: Sullins Connector Solutions; SymbolCreator: a0412235; Pitch_mm: 2.54; Gender: Male; Shrouded: N; Row_Count: 1; Current_A: 3; Voltage_V: 1800; Cert_UL: Y; Green_Lifecycle: Active; Green_REACh: Passed
J19-J21 = 1751248: as J14 on sheet TIDA-010055_Non-ISO_AFE-Power+Protection _Pg7
L8 = CMP-0064461-2: Inductor, Shielded Drum Core, Ferrite, 15 uH, 1.4 A, 0.118 ohm, SMD; Manufacturer: Wurth Elektronik; Isat: 1.7A @ 35% inductance drop; Irms: 1.4A @ 40C rise; Green_Lifecycle: Active; SizeAreaWB_mm2: 33.64; DCR_ohm: 1.18d; Green_REACh: Passed; Value: 15uH; Imax_A: 1.4A; SizeZ_mm: 4.1; SizeX_mm: 4.8; SizeArea_mm2: 23.04; Ind_H: 15µH; AEC Category: Q200
R105 = CRCW0603402KFKEA: RES, 402 k, 1%, 0.1 W, 0603; Manufacturer: Vishay-Dale; CompType: Resistor; Value: 402k; Res_ohm: 402000; Tolerance_%: 1; Power_W: 0.1; Value2: 0.1W; VDC_V: 75; TempCo: 100 ppm/C; SizeArea_mm2: 1.28; SizeX_mm: 1.6; SizeY_mm: 0.8; EIA_Code: E96; U/M: EA; AEC Category: Q200; Green_Lifecycle: Active; Green_REACh: Passed
R106 = CRCW060349R9FKEA: RES, 49.9, 1%, 0.1 W, 0603; Manufacturer: Vishay-Dale; CompType: Resistor; Value: 49.9; Value_Code: 49R9; Tolerance_%: 1; Power_W: 0.1; Value2: 0.1W; VDC_V: 75; TempCo: 100 ppm/C; SizeArea_mm2: 1.28; SizeX_mm: 1.6; SizeY_mm: 0.8; EIA_Code: E96; U/M: EA; AEC Category: Q200; Green_Lifecycle: Active; Green_REACh: Passed
R107 = CRCW0603133KFKEA: RES, 133 k, 1%, 0.1 W, 0603; Manufacturer: Vishay-Dale; CompType: Resistor; Value: 133k; Res_ohm: 133000; Tolerance_%: 1; Power_W: 0.1; Value2: 0.1W; VDC_V: 75; TempCo: 100 ppm/C; SizeArea_mm2: 1.28; SizeX_mm: 1.6; SizeY_mm: 0.8; EIA_Code: E96; U/M: EA; AEC Category: Q200; Green_Lifecycle: Active; Green_REACh: Passed
R108 = CRCW0603102KFKEA: RES, 102 k, 1%, 0.1 W, 0603; Manufacturer: Vishay-Dale; CompType: Resistor; Value: 102k; Res_ohm: 102000; Tolerance_%: 1; Power_W: 0.1; Value2: 0.1W; VDC_V: 75; TempCo: 100 ppm/C; SizeArea_mm2: 1.28; SizeX_mm: 1.6; SizeY_mm: 0.8; EIA_Code: E96; U/M: EA; AEC Category: Q200; Green_Lifecycle: Active; Green_REACh: Passed
R109 = CRCW060325K5FKEA: RES, 25.5 k, 1%, 0.1 W, 0603; Manufacturer: Vishay-Dale; CompType: Resistor; Value: 25.5k; Res_ohm: 25500; Value_Code: 25k5; Tolerance_%: 1; Power_W: 0.1; Value2: 0.1W; VDC_V: 75; TempCo: 100 ppm/C; SizeArea_mm2: 1.28; SizeX_mm: 1.6; SizeY_mm: 0.8; EIA_Code: E96; U/M: EA; AEC Category: Q200; Green_Lifecycle: Active; Green_REACh: Passed
TP34 TP36 = 5000: as TP15 on sheet TIDA-010055_Non-ISO_AFE-Power+Protection _Pg7
TP35 TP37 = 5001: as TP41 on sheet TIDA-010055_Non-ISO_AFE-Power+Protection _Pg7
TP42 = 5002: as TP8 on sheet TIDA-010055_Non-ISO_AFE-Power+Protection _Pg7
U44 = CMP-0065098-3: 4V to 36 V 0.6 A Synchronous Step-Down Converter, DBV0006A (SOT-23-6); Manufacturer: Texas Instruments; Alternate PartNumber: TPS560430XFDBVT; SizeX_mm: 2.8; SizeY_mm: 2.9; CompType: IC; SizeZ_mm: 1.45; SizeArea_mm2: 8.12; SizeAreaWB_mm2: 14.82; U/M: EA
U45 = CMP-0013051-2: 1uA IQ, 200 mA, Ultralow IQ Low-Dropout Regulator, DBV0005A (SOT-5); Manufacturer: Texas Instruments; SizeX_mm: 2.8; SizeY_mm: 2.9; CompType: IC; SizeZ_mm: 1.45; SizeArea_mm2: 8.12; SizeAreaWB_mm2: 14.82; U/M: EA
U46 U47 = CMP-0013424-7: as U22 on sheet TIDA-010055_Non-ISO_AFE-Power+Protection _Pg7
U48 U49 = CMP-0077836-1: 14-V Precision Surge Protection Clamp, DRV0006A (WSON-6); Alternate Manufacturer: Texas Instruments; SizeAreaWB_mm2: 9.0; SizeZ_mm: 0.8; SizeX_mm: 2.0; SizeArea_mm2: 4.0; CompType: IC; AEC Qualified: N; AEC Category: Q200

## Sheet TIDA-010055_Non-ISO_AFE-Power+Protection _EVM_Hardware_Pg9.SchDoc: Hardware
size 431 x 279 mm; Date: Not shown in title block; ApprovedBy: Not shown in title block; CheckedBy: Not shown in title block; Author: Not shown in title block; CompanyName: Not shown in title block; DrawnBy: Sreenivasa; Engineer: Not shown in title block; Organization: Not shown in title block; Address1: Not shown in title block; Address2: Not shown in title block; Address3: Not shown in title block; Address4: Not shown in title block; DocumentNumber: 1; Revision: Use project parameter SCH_Rev; SheetNumber: 9; SheetTotal: 9; PageSetup: Record=PageOptions¦CenterHorizontal=True¦CenterVertical=True¦PrintScale=1.00¦XCorrection=1.00¦YCorrection=1.00¦PrintKind=0¦BorderSize=5000000¦LeftOffset=0¦BottomOffset=0¦Orientation=2¦PaperLength=1000¦PaperWidth=1000¦Scale=100¦PaperSource=15¦PrintQuality=600¦MediaType=1¦DitherType=10¦PaperKind=Letter¦PrintScaleMode=1
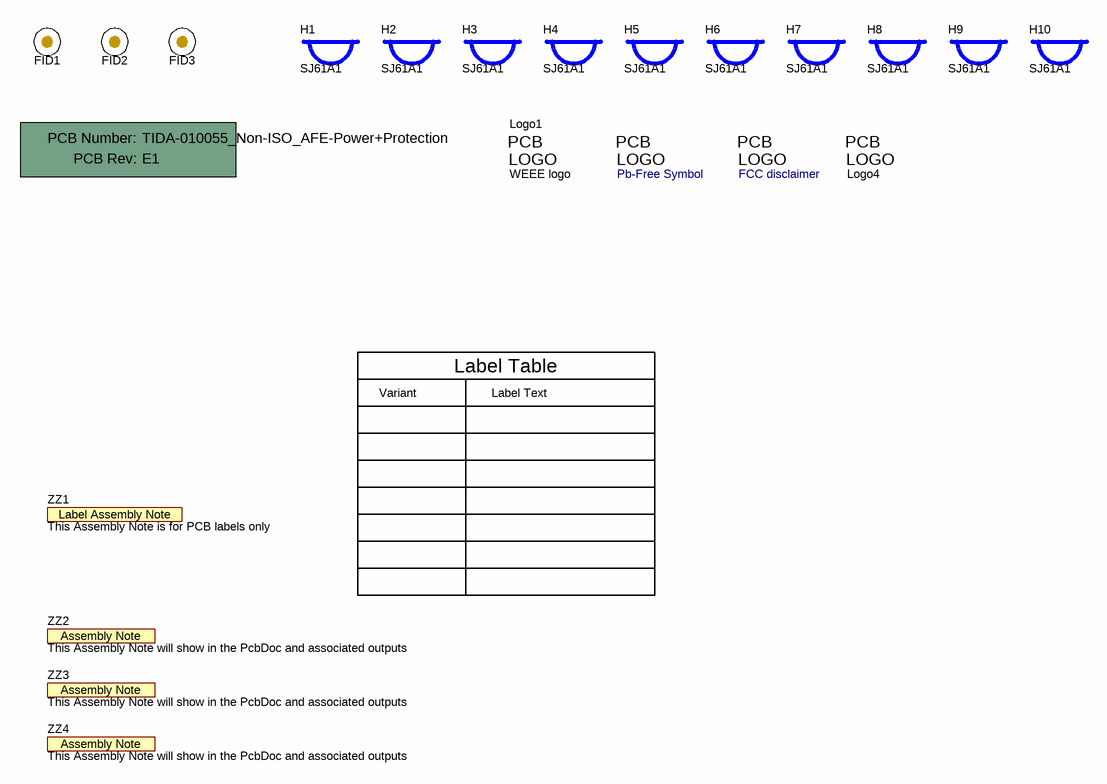
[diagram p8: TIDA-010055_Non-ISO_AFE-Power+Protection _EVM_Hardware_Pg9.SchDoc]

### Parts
!PCB1  Printed Circuit Board  (value not drawn)  (mechanical)
FID1  Fiducial  [Fiducial10-30]  (value not drawn)
FID2  Fiducial  [Fiducial10-30]  (value not drawn)
FID3  Fiducial  [Fiducial10-30]  (value not drawn)
H1  SJ61A1  [Bumpon_SJ61A1]
H2  SJ61A1  [Bumpon_SJ61A1]
H3  SJ61A1  [Bumpon_SJ61A1]
H4  SJ61A1  [Bumpon_SJ61A1]
H5  SJ61A1  [Bumpon_SJ61A1]
H6  SJ61A1  [Bumpon_SJ61A1]
H7  SJ61A1  [Bumpon_SJ61A1]
H8  SJ61A1  [Bumpon_SJ61A1]
H9  SJ61A1  [Bumpon_SJ61A1]
H10  SJ61A1  [Bumpon_SJ61A1]
Logo1  WEEE logo  [WEEE_Minimum]  (no BOM)
Logo2  Pb-Free Symbol  [Pb-Free_Overlay_Small]  (no BOM)
Logo3  FCC disclaimer  [FCC_disclaimer_stacked]  (no BOM)
Logo4  ESD Susceptible  [ESD_Overlay_Medium]  (value not drawn)  (no BOM)
ZZ1  This Assembly Note is for PCB labels only  [AssemblyNoteLabel]  (no BOM)
ZZ2  This Assembly Note will show in the PcbDoc and associated outputs  [AssemblyNote]  (no BOM)
ZZ3  This Assembly Note will show in the PcbDoc and associated outputs  [AssemblyNote]  (no BOM)
ZZ4  This Assembly Note will show in the PcbDoc and associated outputs  [AssemblyNote]  (no BOM)

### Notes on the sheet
- Variant
- Label Table
- Label Text

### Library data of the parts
!PCB1 = PCB: Manufacturer: Any; PartNumber: TIDA-010055_Non-ISO_AFE-Power+Protection; SymbolCreator: a0412235
FID1-FID3 = Fiducial: Fiducial mark.  There is nothing to buy or mount.; SymbolCreator: codlsc
H1-H10 = SJ61A1: Bumpon, Cylindrical, 0.312 X 0.200, Black; Manufacturer: 3M; SymbolCreator: a0412235; Green_Lifecycle: Not Set; Green_REACh: Incomplete
Logo1 = CMP-0074769-1
Logo2 = Pb-Free: SymbolCreator: a0412235
Logo3 = FCC_disclaimer: SymbolCreator: codlsc
Logo4 = ESD_Susceptible: ESD Susceptible Symbol; SymbolCreator: a0412235
ZZ1 = AssemblyNoteLabel: SymbolCreator: a0412235
ZZ2-ZZ4 = AssemblyNote: SymbolCreator: codlsc

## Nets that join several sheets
+5V_IN: TIDA-010055_Non-ISO_AFE-Power+Protection _Pg3 (R112.2 R113.2 TP44.1), TIDA-010055_Non-ISO_AFE-Power+Protection _Pg4 (L3.1), TIDA-010055_Non-ISO_AFE-Power+Protection _Pg5 (C58.1 R19.2 U10.2)
+14V: TIDA-010055_Non-ISO_AFE-Power+Protection _Pg4 (5 pins), TIDA-010055_Non-ISO_AFE-Power+Protection _Pg5 (R26.1 R38.1)
-14V: TIDA-010055_Non-ISO_AFE-Power+Protection _Pg4 (5 pins), TIDA-010055_Non-ISO_AFE-Power+Protection _Pg5 (R33.1)
AGND: TIDA-010055_Non-ISO_AFE-Power+Protection _Pg5 (62 pins), TIDA-010055_Non-ISO_AFE-Power+Protection _Pg8 (6 pins)
GND: TIDA-010055_Non-ISO_AFE-Power+Protection _Pg3 (31 pins), TIDA-010055_Non-ISO_AFE-Power+Protection _Pg4 (24 pins), TIDA-010055_Non-ISO_AFE-Power+Protection _Pg5 (R51.2)
GND1: TIDA-010055_Non-ISO_AFE-Power+Protection _Pg6 (63 pins), TIDA-010055_Non-ISO_AFE-Power+Protection _Pg7 (47 pins)
VDC_5V_1: TIDA-010055_Non-ISO_AFE-Power+Protection _Pg6 (14 pins), TIDA-010055_Non-ISO_AFE-Power+Protection _Pg7 (C98.1 U18.8)

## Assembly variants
001: not fitted C1 C11 FID1 FID2 FID3 R5 R24 R40 R42 R110 R113 R118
